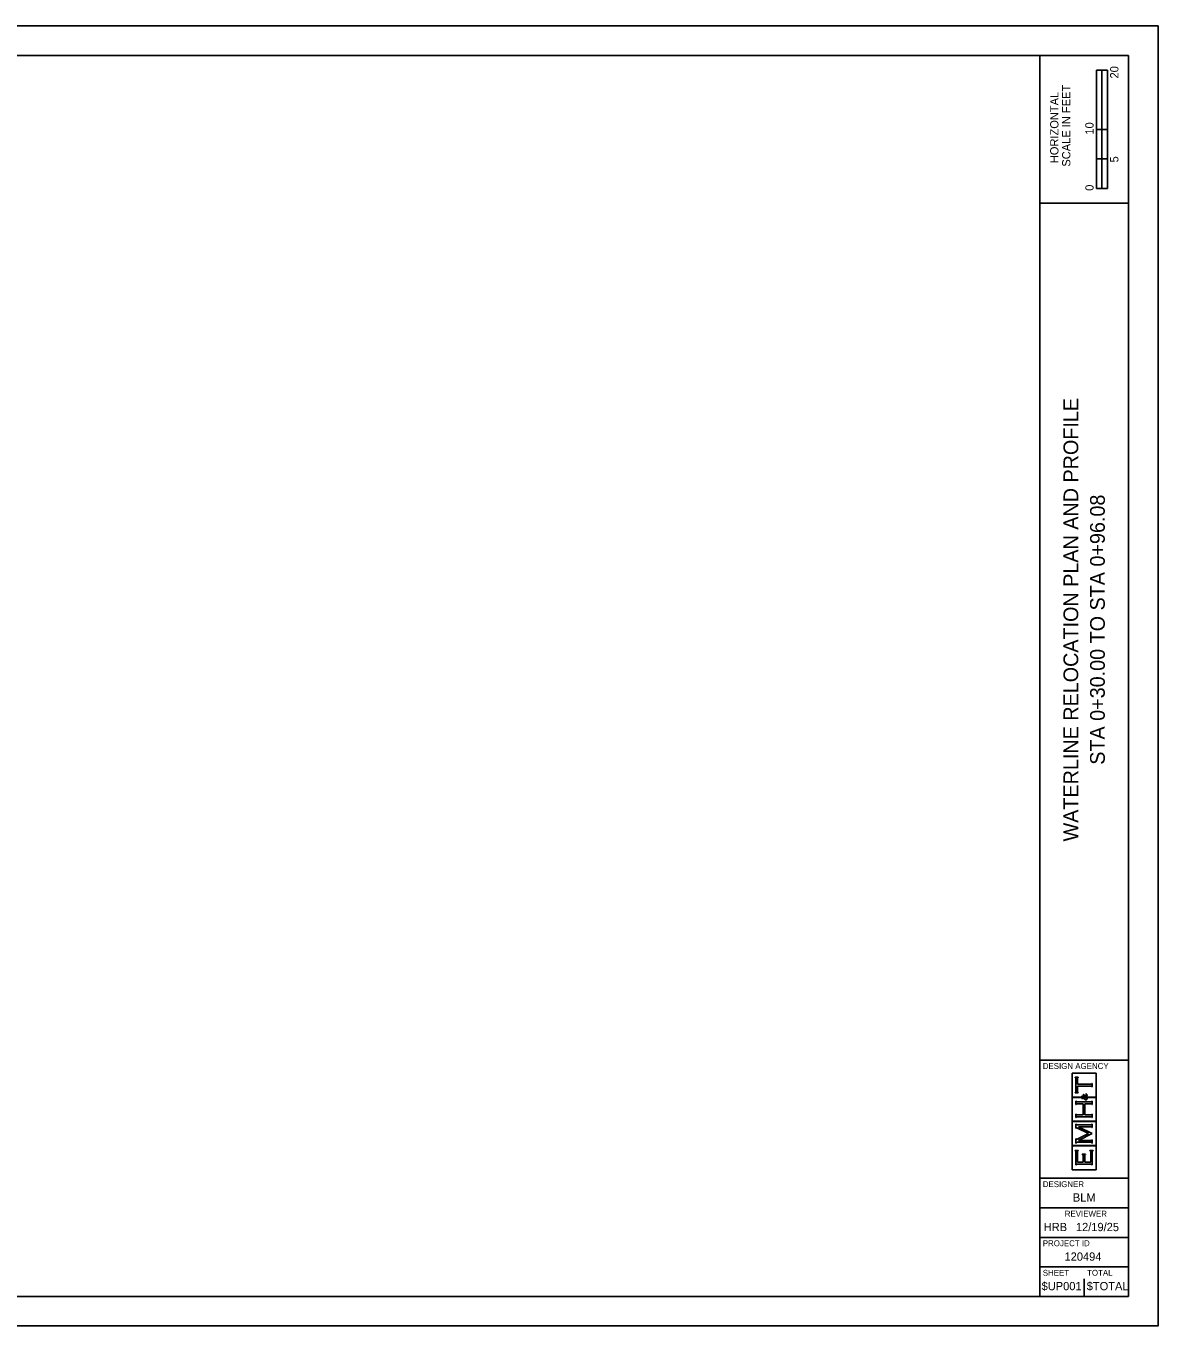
# Model space of a CAD drawing. Extents: x -4.3 to 34, y -1.9 to 20.1.
# Drawn here: x 14.84 to 34, y -1.91 to 20.09 of the extents above; entities that cross this region are included whole.
import ezdxf

# ---------------------------------------------------------------- set-up
doc = ezdxf.new("R2010")
doc.units = 0
for name, color, linetype in [('PF_P_Sta_Elev_Text', 7, 'Continuous'), ('SH_Major_Grid_Line', 7, 'Continuous'), ('SH_Text', 7, 'Continuous')]:
    doc.layers.add(name, color=color, linetype=linetype)

msp = doc.modelspace()

# ---------------------------------------------------------------- linework, layer by layer
at = {"layer": 'PF_P_Sta_Elev_Text'}
for p, q in [((32.957, 17.345), (32.957, 19.345)), ((33.144, 19.345), (32.957, 19.345)), ((32.957, 18.345), (32.957, 19.345)), ((32.957, 19.345), (33.05, 19.345)), ((33.05, 19.345), (33.051, 19.345)), ((33.051, 19.345), (33.051, 18.345)), ((33.144, 19.345), (33.144, 17.345)), ((33.051, 18.345), (32.957, 18.345)), ((33.143, 18.345), (33.05, 18.345)), ((33.05, 18.345), (33.05, 17.845)), ((33.143, 17.845), (33.143, 18.345)), ((33.05, 17.845), (32.957, 17.845)), ((32.957, 17.845), (32.957, 17.345)), ((33.05, 17.345), (33.05, 17.845)), ((33.05, 17.845), (33.143, 17.845)), ((33.144, 17.345), (32.957, 17.345)), ((32.957, 17.345), (33.05, 17.345)), ((32.952, 2.374), (32.547, 2.374)), ((32.547, 2.374), (32.547, 1.97)), ((32.598, 2.299), (32.598, 2.305)), ((32.598, 2.305), (32.65, 2.305)), ((32.603, 2.298), (32.598, 2.299)), ((32.606, 2.296), (32.603, 2.298)), ((32.608, 2.294), (32.606, 2.296)), ((32.61, 2.291), (32.608, 2.294)), ((32.611, 2.287), (32.61, 2.291)), ((32.611, 2.282), (32.611, 2.287)), ((32.611, 2.062), (32.611, 2.282)), ((32.638, 2.291), (32.637, 2.287)), ((32.637, 2.287), (32.637, 2.281)), ((32.637, 2.281), (32.637, 2.188)), ((32.64, 2.294), (32.638, 2.291)), ((32.642, 2.296), (32.64, 2.294)), ((32.645, 2.298), (32.642, 2.296)), ((32.65, 2.299), (32.645, 2.298)), ((32.65, 2.305), (32.65, 2.299)), ((32.88, 2.196), (32.881, 2.201)), ((32.881, 2.201), (32.888, 2.201)), ((32.888, 2.201), (32.888, 2.143)), ((32.952, 1.97), (32.952, 2.374)), ((32.598, 2.045), (32.603, 2.046)), ((32.598, 2.038), (32.598, 2.045)), ((32.65, 2.038), (32.598, 2.038)), ((32.603, 2.046), (32.606, 2.048)), ((32.606, 2.048), (32.608, 2.05)), ((32.608, 2.05), (32.61, 2.053)), ((32.61, 2.053), (32.611, 2.057)), ((32.611, 2.057), (32.611, 2.062)), ((32.637, 2.188), (32.864, 2.188)), ((32.864, 2.156), (32.637, 2.156)), ((32.637, 2.156), (32.637, 2.062)), ((32.637, 2.062), (32.637, 2.057)), ((32.637, 2.057), (32.638, 2.053)), ((32.638, 2.053), (32.64, 2.05)), ((32.64, 2.05), (32.642, 2.048)), ((32.642, 2.048), (32.645, 2.046)), ((32.645, 2.046), (32.65, 2.045)), ((32.65, 2.045), (32.65, 2.038)), ((32.705, 1.978), (32.708, 1.981)), ((32.708, 1.981), (32.711, 1.985)), ((32.711, 1.985), (32.715, 1.986)), ((32.715, 1.986), (32.72, 1.986)), ((32.72, 1.986), (32.725, 1.986)), ((32.725, 1.986), (32.729, 1.985)), ((32.729, 1.985), (32.732, 1.982)), ((32.732, 1.982), (32.736, 1.978)), ((32.738, 1.988), (32.738, 2.016)), ((32.738, 2.016), (32.741, 2.016)), ((32.741, 1.988), (32.738, 1.988)), ((32.741, 2.016), (32.741, 2.012)), ((32.741, 2.012), (32.742, 2.01)), ((32.742, 1.991), (32.741, 1.99)), ((32.741, 1.99), (32.741, 1.988)), ((32.742, 2.01), (32.743, 2.008)), ((32.743, 1.992), (32.742, 1.991)), ((32.743, 2.008), (32.745, 2.006)), ((32.745, 1.994), (32.743, 1.992)), ((32.745, 2.006), (32.749, 2.003)), ((32.746, 1.994), (32.745, 1.994)), ((32.748, 1.994), (32.746, 1.994)), ((32.755, 1.994), (32.748, 1.994)), ((32.749, 2.003), (32.756, 1.999)), ((32.763, 1.99), (32.755, 1.994)), ((32.756, 1.999), (32.763, 1.995)), ((32.763, 1.995), (32.77, 1.99)), ((32.772, 1.982), (32.763, 1.99)), ((32.764, 1.976), (32.772, 1.982)), ((32.77, 1.99), (32.776, 1.985)), ((32.776, 1.985), (32.781, 1.989)), ((32.779, 2.018), (32.781, 2.021)), ((32.782, 2.017), (32.779, 2.018)), ((32.781, 2.021), (32.787, 2.019)), ((32.781, 1.989), (32.784, 1.993)), ((32.785, 2.016), (32.782, 2.017)), ((32.784, 1.993), (32.786, 1.996)), ((32.786, 2.013), (32.785, 2.016)), ((32.788, 2.011), (32.786, 2.013)), ((32.786, 1.996), (32.788, 1.999)), ((32.791, 1.98), (32.786, 1.976)), ((32.787, 2.019), (32.792, 2.016)), ((32.789, 2.009), (32.788, 2.011)), ((32.788, 1.999), (32.789, 2.002)), ((32.789, 2.006), (32.789, 2.009)), ((32.789, 2.002), (32.789, 2.006)), ((32.794, 1.985), (32.791, 1.98)), ((32.792, 2.016), (32.795, 2.013)), ((32.796, 1.988), (32.794, 1.985)), ((32.795, 2.013), (32.798, 2.009)), ((32.798, 1.992), (32.796, 1.988)), ((32.798, 2.009), (32.799, 2.005)), ((32.799, 1.996), (32.798, 1.992)), ((32.799, 2.005), (32.799, 2)), ((32.799, 2), (32.799, 1.996)), ((32.864, 2.188), (32.869, 2.188)), ((32.87, 2.156), (32.864, 2.156)), ((32.869, 2.188), (32.873, 2.189)), ((32.874, 2.155), (32.87, 2.156)), ((32.873, 2.189), (32.876, 2.19)), ((32.876, 2.153), (32.874, 2.155)), ((32.876, 2.19), (32.878, 2.192)), ((32.878, 2.152), (32.876, 2.153)), ((32.878, 2.192), (32.88, 2.196)), ((32.88, 2.148), (32.878, 2.152)), ((32.881, 2.143), (32.88, 2.148)), ((32.888, 2.143), (32.881, 2.143)), ((32.547, 1.97), (32.696, 1.97)), ((32.696, 1.964), (32.547, 1.964)), ((32.547, 1.964), (32.547, 1.56)), ((32.611, 1.844), (32.611, 1.902)), ((32.611, 1.902), (32.617, 1.902)), ((32.617, 1.844), (32.611, 1.844)), ((32.617, 1.902), (32.619, 1.897)), ((32.618, 1.849), (32.617, 1.844)), ((32.62, 1.853), (32.618, 1.849)), ((32.619, 1.897), (32.62, 1.893)), ((32.62, 1.893), (32.623, 1.892)), ((32.623, 1.854), (32.62, 1.853)), ((32.623, 1.892), (32.625, 1.89)), ((32.625, 1.856), (32.623, 1.854)), ((32.625, 1.89), (32.629, 1.889)), ((32.629, 1.857), (32.625, 1.856)), ((32.629, 1.889), (32.635, 1.889)), ((32.635, 1.857), (32.629, 1.857)), ((32.635, 1.889), (32.864, 1.889)), ((32.732, 1.857), (32.635, 1.857)), ((32.696, 1.97), (32.696, 1.964)), ((32.703, 1.974), (32.705, 1.978)), ((32.703, 1.968), (32.703, 1.974)), ((32.703, 1.963), (32.703, 1.968)), ((32.705, 1.958), (32.703, 1.963)), ((32.708, 1.953), (32.705, 1.958)), ((32.709, 1.974), (32.708, 1.971)), ((32.708, 1.971), (32.708, 1.968)), ((32.708, 1.968), (32.708, 1.964)), ((32.708, 1.964), (32.71, 1.961)), ((32.712, 1.947), (32.708, 1.953)), ((32.712, 1.976), (32.709, 1.974)), ((32.71, 1.961), (32.712, 1.959)), ((32.714, 1.978), (32.712, 1.976)), ((32.712, 1.959), (32.715, 1.957)), ((32.718, 1.945), (32.712, 1.947)), ((32.716, 1.979), (32.714, 1.978)), ((32.715, 1.957), (32.718, 1.956)), ((32.72, 1.979), (32.716, 1.979)), ((32.718, 1.956), (32.721, 1.956)), ((32.726, 1.945), (32.718, 1.945)), ((32.724, 1.979), (32.72, 1.979)), ((32.721, 1.956), (32.723, 1.956)), ((32.723, 1.956), (32.725, 1.957)), ((32.728, 1.977), (32.724, 1.979)), ((32.725, 1.957), (32.728, 1.957)), ((32.729, 1.945), (32.726, 1.945)), ((32.731, 1.974), (32.728, 1.977)), ((32.728, 1.957), (32.731, 1.958)), ((32.731, 1.945), (32.729, 1.945)), ((32.734, 1.972), (32.731, 1.974)), ((32.731, 1.958), (32.735, 1.959)), ((32.734, 1.946), (32.731, 1.945)), ((32.732, 1.667), (32.732, 1.857)), ((32.737, 1.967), (32.734, 1.972)), ((32.737, 1.947), (32.734, 1.946)), ((32.735, 1.959), (32.74, 1.962)), ((32.736, 1.978), (32.74, 1.972)), ((32.74, 1.962), (32.737, 1.967)), ((32.741, 1.948), (32.737, 1.947)), ((32.74, 1.972), (32.744, 1.964)), ((32.746, 1.95), (32.741, 1.948)), ((32.744, 1.964), (32.754, 1.97)), ((32.752, 1.939), (32.746, 1.95)), ((32.756, 1.955), (32.751, 1.952)), ((32.751, 1.952), (32.754, 1.947)), ((32.757, 1.932), (32.752, 1.939)), ((32.754, 1.97), (32.764, 1.976)), ((32.754, 1.947), (32.757, 1.943)), ((32.761, 1.958), (32.756, 1.955)), ((32.757, 1.943), (32.761, 1.94)), ((32.763, 1.928), (32.757, 1.932)), ((32.864, 1.857), (32.759, 1.857)), ((32.759, 1.857), (32.759, 1.667)), ((32.764, 1.96), (32.761, 1.958)), ((32.761, 1.94), (32.765, 1.937)), ((32.768, 1.924), (32.763, 1.928)), ((32.768, 1.962), (32.764, 1.96)), ((32.765, 1.937), (32.769, 1.936)), ((32.774, 1.966), (32.768, 1.962)), ((32.774, 1.922), (32.768, 1.924)), ((32.769, 1.936), (32.773, 1.936)), ((32.773, 1.936), (32.778, 1.936)), ((32.782, 1.972), (32.774, 1.966)), ((32.779, 1.922), (32.774, 1.922)), ((32.778, 1.936), (32.782, 1.938)), ((32.785, 1.922), (32.779, 1.922)), ((32.786, 1.968), (32.782, 1.972)), ((32.782, 1.938), (32.786, 1.941)), ((32.79, 1.924), (32.785, 1.922)), ((32.786, 1.976), (32.791, 1.97)), ((32.788, 1.964), (32.786, 1.968)), ((32.786, 1.941), (32.789, 1.944)), ((32.79, 1.962), (32.788, 1.964)), ((32.789, 1.944), (32.791, 1.948)), ((32.791, 1.959), (32.79, 1.962)), ((32.793, 1.929), (32.79, 1.924)), ((32.791, 1.97), (32.795, 1.965)), ((32.791, 1.956), (32.791, 1.959)), ((32.791, 1.953), (32.791, 1.956)), ((32.791, 1.948), (32.791, 1.953)), ((32.797, 1.933), (32.793, 1.929)), ((32.795, 1.965), (32.797, 1.961)), ((32.797, 1.961), (32.798, 1.956)), ((32.799, 1.939), (32.797, 1.933)), ((32.798, 1.956), (32.799, 1.952)), ((32.803, 1.964), (32.799, 1.97)), ((32.799, 1.97), (32.952, 1.97)), ((32.799, 1.952), (32.799, 1.946)), ((32.799, 1.946), (32.799, 1.939)), ((32.952, 1.964), (32.803, 1.964)), ((32.864, 1.889), (32.869, 1.889)), ((32.87, 1.857), (32.864, 1.857)), ((32.869, 1.889), (32.873, 1.89)), ((32.874, 1.856), (32.87, 1.857)), ((32.873, 1.89), (32.876, 1.892)), ((32.876, 1.854), (32.874, 1.856)), ((32.876, 1.892), (32.878, 1.893)), ((32.878, 1.853), (32.876, 1.854)), ((32.878, 1.893), (32.88, 1.897)), ((32.88, 1.849), (32.878, 1.853)), ((32.88, 1.897), (32.881, 1.902)), ((32.881, 1.844), (32.88, 1.849)), ((32.881, 1.902), (32.888, 1.902)), ((32.888, 1.844), (32.881, 1.844)), ((32.888, 1.902), (32.888, 1.844)), ((32.952, 1.56), (32.952, 1.964)), ((32.547, 1.56), (32.952, 1.56)), ((32.952, 1.554), (32.547, 1.554)), ((32.547, 1.554), (32.547, 1.15)), ((32.611, 1.622), (32.611, 1.68)), ((32.611, 1.68), (32.617, 1.68)), ((32.617, 1.622), (32.611, 1.622)), ((32.617, 1.68), (32.619, 1.674)), ((32.618, 1.627), (32.617, 1.622)), ((32.62, 1.63), (32.618, 1.627)), ((32.619, 1.674), (32.62, 1.671)), ((32.62, 1.671), (32.623, 1.669)), ((32.623, 1.632), (32.62, 1.63)), ((32.623, 1.669), (32.625, 1.668)), ((32.625, 1.634), (32.623, 1.632)), ((32.625, 1.668), (32.629, 1.667)), ((32.629, 1.635), (32.625, 1.634)), ((32.629, 1.667), (32.635, 1.667)), ((32.635, 1.635), (32.629, 1.635)), ((32.635, 1.667), (32.732, 1.667)), ((32.864, 1.635), (32.635, 1.635)), ((32.75, 1.595), (32.75, 1.595)), ((32.759, 1.667), (32.864, 1.667)), ((32.864, 1.667), (32.87, 1.667)), ((32.87, 1.635), (32.864, 1.635)), ((32.87, 1.667), (32.874, 1.667)), ((32.874, 1.634), (32.87, 1.635)), ((32.874, 1.667), (32.876, 1.669)), ((32.876, 1.632), (32.874, 1.634)), ((32.876, 1.669), (32.878, 1.671)), ((32.878, 1.631), (32.876, 1.632)), ((32.878, 1.671), (32.88, 1.674)), ((32.88, 1.627), (32.878, 1.631)), ((32.88, 1.674), (32.881, 1.68)), ((32.881, 1.622), (32.88, 1.627)), ((32.881, 1.68), (32.888, 1.68)), ((32.888, 1.622), (32.881, 1.622)), ((32.888, 1.68), (32.888, 1.622)), ((32.952, 1.15), (32.952, 1.554)), ((32.611, 1.44), (32.611, 1.512)), ((32.611, 1.512), (32.617, 1.512)), ((32.617, 1.44), (32.611, 1.44)), ((32.617, 1.512), (32.619, 1.507)), ((32.62, 1.447), (32.617, 1.44)), ((32.619, 1.507), (32.62, 1.504)), ((32.62, 1.504), (32.623, 1.502)), ((32.622, 1.45), (32.62, 1.447)), ((32.626, 1.45), (32.622, 1.45)), ((32.623, 1.502), (32.625, 1.5)), ((32.625, 1.5), (32.629, 1.499)), ((32.629, 1.45), (32.626, 1.45)), ((32.629, 1.499), (32.635, 1.499)), ((32.633, 1.448), (32.629, 1.45)), ((32.64, 1.445), (32.633, 1.448)), ((32.635, 1.499), (32.864, 1.499)), ((32.825, 1.352), (32.64, 1.445)), ((32.641, 1.26), (32.825, 1.352)), ((32.864, 1.468), (32.654, 1.468)), ((32.654, 1.468), (32.888, 1.35)), ((32.888, 1.35), (32.654, 1.233)), ((32.864, 1.499), (32.869, 1.499)), ((32.87, 1.468), (32.864, 1.468)), ((32.869, 1.499), (32.873, 1.5)), ((32.874, 1.467), (32.87, 1.468)), ((32.873, 1.5), (32.876, 1.502)), ((32.876, 1.465), (32.874, 1.467)), ((32.876, 1.502), (32.878, 1.504)), ((32.878, 1.463), (32.876, 1.465)), ((32.878, 1.504), (32.88, 1.507)), ((32.88, 1.46), (32.878, 1.463)), ((32.88, 1.507), (32.881, 1.512)), ((32.881, 1.455), (32.88, 1.46)), ((32.881, 1.512), (32.888, 1.512)), ((32.888, 1.455), (32.881, 1.455)), ((32.888, 1.512), (32.888, 1.455)), ((32.547, 1.15), (32.952, 1.15)), ((32.952, 1.144), (32.547, 1.144)), ((32.547, 1.144), (32.547, 0.739)), ((32.611, 1.191), (32.611, 1.263)), ((32.611, 1.263), (32.617, 1.263)), ((32.617, 1.191), (32.611, 1.191)), ((32.617, 1.263), (32.62, 1.256)), ((32.618, 1.196), (32.617, 1.191)), ((32.62, 1.2), (32.618, 1.196)), ((32.62, 1.256), (32.622, 1.253)), ((32.623, 1.202), (32.62, 1.2)), ((32.622, 1.253), (32.626, 1.253)), ((32.625, 1.203), (32.623, 1.202)), ((32.629, 1.204), (32.625, 1.203)), ((32.626, 1.253), (32.627, 1.253)), ((32.627, 1.253), (32.633, 1.255)), ((32.635, 1.204), (32.629, 1.204)), ((32.633, 1.255), (32.641, 1.26)), ((32.864, 1.204), (32.635, 1.204)), ((32.654, 1.233), (32.864, 1.233)), ((32.864, 1.233), (32.869, 1.233)), ((32.87, 1.204), (32.864, 1.204)), ((32.869, 1.233), (32.873, 1.234)), ((32.874, 1.203), (32.87, 1.204)), ((32.873, 1.234), (32.876, 1.236)), ((32.876, 1.202), (32.874, 1.203)), ((32.876, 1.236), (32.878, 1.238)), ((32.878, 1.2), (32.876, 1.202)), ((32.878, 1.238), (32.88, 1.241)), ((32.88, 1.196), (32.878, 1.2)), ((32.88, 1.241), (32.881, 1.246)), ((32.881, 1.191), (32.88, 1.196)), ((32.881, 1.246), (32.888, 1.246)), ((32.888, 1.191), (32.881, 1.191)), ((32.888, 1.246), (32.888, 1.191)), ((32.952, 0.739), (32.952, 1.144)), ((32.598, 1.057), (32.598, 1.064)), ((32.598, 1.064), (32.65, 1.064)), ((32.603, 1.056), (32.598, 1.057)), ((32.606, 1.054), (32.603, 1.056)), ((32.608, 1.052), (32.606, 1.054)), ((32.61, 1.049), (32.608, 1.052)), ((32.611, 1.045), (32.61, 1.049)), ((32.611, 1.04), (32.611, 1.045)), ((32.611, 0.82), (32.611, 1.04)), ((32.64, 1.052), (32.638, 1.049)), ((32.638, 1.049), (32.638, 1.045)), ((32.638, 1.045), (32.638, 1.04)), ((32.638, 1.04), (32.638, 0.865)), ((32.642, 1.054), (32.64, 1.052)), ((32.645, 1.056), (32.642, 1.054)), ((32.65, 1.057), (32.645, 1.056)), ((32.65, 1.064), (32.65, 1.057)), ((32.719, 0.997), (32.719, 1.003)), ((32.719, 1.003), (32.772, 1.003)), ((32.724, 0.995), (32.719, 0.997)), ((32.728, 0.994), (32.724, 0.995)), ((32.729, 0.991), (32.728, 0.994)), ((32.731, 0.989), (32.729, 0.991)), ((32.732, 0.985), (32.731, 0.989)), ((32.732, 0.979), (32.732, 0.985)), ((32.732, 0.865), (32.732, 0.979)), ((32.76, 0.989), (32.759, 0.985)), ((32.759, 0.985), (32.759, 0.979)), ((32.759, 0.979), (32.759, 0.865)), ((32.761, 0.991), (32.76, 0.989)), ((32.763, 0.994), (32.761, 0.991)), ((32.767, 0.995), (32.763, 0.994)), ((32.772, 0.997), (32.767, 0.995)), ((32.772, 1.003), (32.772, 0.997)), ((32.848, 1.06), (32.848, 1.067)), ((32.848, 1.067), (32.901, 1.067)), ((32.853, 1.059), (32.848, 1.06)), ((32.857, 1.057), (32.853, 1.059)), ((32.859, 1.055), (32.857, 1.057)), ((32.86, 1.052), (32.859, 1.055)), ((32.861, 1.048), (32.86, 1.052)), ((32.861, 1.043), (32.861, 1.048)), ((32.861, 0.865), (32.861, 1.043)), ((32.889, 1.052), (32.888, 1.048)), ((32.888, 1.048), (32.888, 1.042)), ((32.888, 1.042), (32.888, 0.82)), ((32.891, 1.055), (32.889, 1.052)), ((32.892, 1.057), (32.891, 1.055)), ((32.896, 1.059), (32.892, 1.057)), ((32.901, 1.06), (32.896, 1.059)), ((32.901, 1.067), (32.901, 1.06)), ((32.547, 0.739), (32.952, 0.739)), ((32.617, 0.82), (32.611, 0.82)), ((32.619, 0.825), (32.617, 0.82)), ((32.62, 0.828), (32.619, 0.825)), ((32.623, 0.83), (32.62, 0.828)), ((32.625, 0.832), (32.623, 0.83)), ((32.629, 0.833), (32.625, 0.832)), ((32.635, 0.833), (32.629, 0.833)), ((32.864, 0.833), (32.635, 0.833)), ((32.638, 0.865), (32.732, 0.865)), ((32.759, 0.865), (32.861, 0.865)), ((32.87, 0.833), (32.864, 0.833)), ((32.874, 0.832), (32.87, 0.833)), ((32.876, 0.83), (32.874, 0.832)), ((32.878, 0.829), (32.876, 0.83)), ((32.88, 0.825), (32.878, 0.829)), ((32.881, 0.82), (32.88, 0.825)), ((32.888, 0.82), (32.881, 0.82)), ((32.375, -1.23), (32.375, -1.23)), ((32.75, -1.405), (32.75, -1.105))]:
    msp.add_line(p, q, dxfattribs=at)
at = {"layer": 'SH_Major_Grid_Line'}
for p, q in [((32, -1.405), (32, 19.595)), ((32, 17.095), (33.5, 17.095)), ((32, 2.595), (33.5, 2.595)), ((32, 0.595), (33.5, 0.595)), ((32, 0.095), (33.5, 0.095)), ((32, -0.405), (33.5, -0.405)), ((32, -0.905), (33.5, -0.905))]:
    msp.add_line(p, q, dxfattribs=at)
msp.add_lwpolyline([(1.5, 19.595), (33.5, 19.595), (33.5, -1.405), (1.5, -1.405)], close=True, dxfattribs=at)
at = {"layer": 'SH_Text'}
msp.add_lwpolyline([(0, -1.905), (34, -1.905), (34, 20.095), (0, 20.095)], close=True, dxfattribs=at)

# ---------------------------------------------------------------- texts
at = {"layer": 'PF_P_Sta_Elev_Text'}
for s, height, p in [('20', 0.14, (33.33, 19.207)), ('HORIZONTAL', 0.14, (32.315, 17.774)), ('SCALE IN FEET', 0.14, (32.517, 17.715)), ('10', 0.14, (32.91, 18.257)), ('5', 0.14, (33.33, 17.786)), ('0', 0.14, (32.91, 17.306)), ('WATERLINE RELOCATION PLAN AND PROFILE', 0.25, (32.65, 6.295)), ('STA 0+30.00 TO STA 0+96.08', 0.25, (33.1, 7.593))]:
    msp.add_text(s, height=height, rotation=90, dxfattribs=at).set_placement(p)
for s, height, p in [('DESIGN AGENCY', 0.1, (32.05, 2.445)), ('DESIGNER', 0.1, (32.05, 0.445)), ('BLM', 0.14, (32.559, 0.2)), ('REVIEWER', 0.1, (32.422, -0.055)), ('HRB', 0.14, (32.066, -0.3)), ('12/19/25', 0.14, (32.611, -0.3)), ('PROJECT ID', 0.1, (32.05, -0.555)), ('120494', 0.14, (32.418, -0.8)), ('SHEET', 0.1, (32.05, -1.055)), ('TOTAL', 0.1, (32.8, -1.055)), ('$UP001', 0.14, (32.03, -1.3)), ('$TOTAL', 0.14, (32.794, -1.3))]:
    msp.add_text(s, height=height, dxfattribs=at).set_placement(p)

doc.saveas('drawing.dxf')
